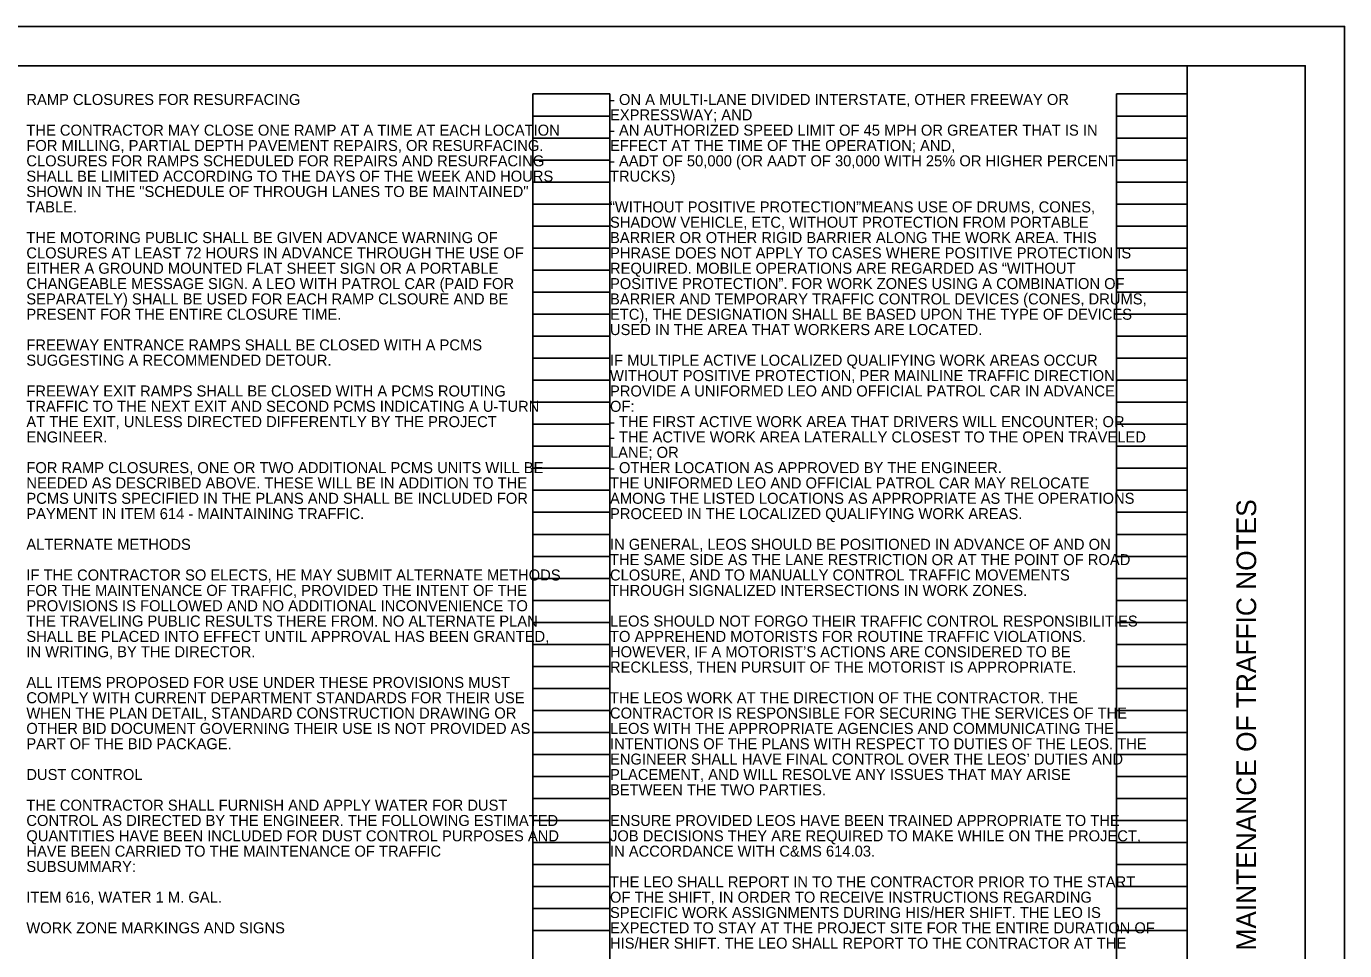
# Model space of a CAD drawing. Extents: x 0 to 34, y 0 to 22.
# Drawn here: x 17.24 to 34, y 10.25 to 22 of the extents above; entities that cross this region are included whole.
import ezdxf

# ---------------------------------------------------------------- set-up
doc = ezdxf.new("R2010")
doc.units = 0
for name, color, linetype in [('SH_Border', 7, 'Continuous'), ('SH_Cut_Line', 7, 'Continuous'), ('SH_Data', 7, 'Continuous'), ('SH_Text', 7, 'Continuous')]:
    doc.layers.add(name, color=color, linetype=linetype)

msp = doc.modelspace()

# ---------------------------------------------------------------- linework, layer by layer
at = {"layer": 'SH_Border'}
msp.add_line((32, 0.5), (32, 21.5), dxfattribs=at)
msp.add_lwpolyline([(1.5, 21.5), (33.5, 21.5), (33.5, 0.5), (1.5, 0.5)], close=True, dxfattribs=at)
at = {"layer": 'SH_Cut_Line'}
msp.add_lwpolyline([(0, 0), (34, 0), (34, 22), (0, 22)], close=True, dxfattribs=at)
at = {"layer": 'SH_Data'}
for p, q in [((23.68, 0.98), (23.68, 21.14)), ((23.68, 21.14), (24.66, 21.14)), ((24.66, 0.98), (24.66, 21.14)), ((31.1, 0.98), (31.1, 21.14)), ((31.1, 21.14), (32, 21.14)), ((32, 0.98), (32, 21.14)), ((23.68, 20.86), (24.66, 20.86)), ((31.1, 20.86), (32, 20.86)), ((23.68, 20.58), (24.66, 20.58)), ((31.1, 20.58), (32, 20.58)), ((23.68, 20.3), (24.66, 20.3)), ((31.1, 20.3), (32, 20.3)), ((23.68, 20.02), (24.66, 20.02)), ((31.1, 20.02), (32, 20.02)), ((23.68, 19.74), (24.66, 19.74)), ((31.1, 19.74), (32, 19.74)), ((23.68, 19.46), (24.66, 19.46)), ((31.1, 19.46), (32, 19.46)), ((23.68, 19.18), (24.66, 19.18)), ((31.1, 19.18), (32, 19.18)), ((23.68, 18.9), (24.66, 18.9)), ((31.1, 18.9), (32, 18.9)), ((23.68, 18.62), (24.66, 18.62)), ((31.1, 18.62), (32, 18.62)), ((23.68, 18.34), (24.66, 18.34)), ((31.1, 18.34), (32, 18.34)), ((23.68, 18.06), (24.66, 18.06)), ((31.1, 18.06), (32, 18.06)), ((23.68, 17.78), (24.66, 17.78)), ((31.1, 17.78), (32, 17.78)), ((23.68, 17.5), (24.66, 17.5)), ((31.1, 17.5), (32, 17.5)), ((23.68, 17.22), (24.66, 17.22)), ((31.1, 17.22), (32, 17.22)), ((23.68, 16.94), (24.66, 16.94)), ((31.1, 16.94), (32, 16.94)), ((23.68, 16.66), (24.66, 16.66)), ((31.1, 16.66), (32, 16.66)), ((23.68, 16.38), (24.66, 16.38)), ((31.1, 16.38), (32, 16.38)), ((23.68, 16.1), (24.66, 16.1)), ((31.1, 16.1), (32, 16.1)), ((23.68, 15.82), (24.66, 15.82)), ((31.1, 15.82), (32, 15.82)), ((23.68, 15.54), (24.66, 15.54)), ((31.1, 15.54), (32, 15.54)), ((23.68, 15.26), (24.66, 15.26)), ((31.1, 15.26), (32, 15.26)), ((23.68, 14.98), (24.66, 14.98)), ((31.1, 14.98), (32, 14.98)), ((23.68, 14.7), (24.66, 14.7)), ((31.1, 14.7), (32, 14.7)), ((23.68, 14.42), (24.66, 14.42)), ((31.1, 14.42), (32, 14.42)), ((23.68, 14.14), (24.66, 14.14)), ((31.1, 14.14), (32, 14.14)), ((23.68, 13.86), (24.66, 13.86)), ((31.1, 13.86), (32, 13.86)), ((23.68, 13.58), (24.66, 13.58)), ((31.1, 13.58), (32, 13.58)), ((23.68, 13.3), (24.66, 13.3)), ((31.1, 13.3), (32, 13.3)), ((23.68, 13.02), (24.66, 13.02)), ((31.1, 13.02), (32, 13.02)), ((23.68, 12.74), (24.66, 12.74)), ((31.1, 12.74), (32, 12.74)), ((23.68, 12.46), (24.66, 12.46)), ((31.1, 12.46), (32, 12.46)), ((23.68, 12.18), (24.66, 12.18)), ((31.1, 12.18), (32, 12.18)), ((23.68, 11.9), (24.66, 11.9)), ((31.1, 11.9), (32, 11.9)), ((23.68, 11.62), (24.66, 11.62)), ((31.1, 11.62), (32, 11.62)), ((23.68, 11.34), (24.66, 11.34)), ((31.1, 11.34), (32, 11.34)), ((23.68, 11.06), (24.66, 11.06)), ((31.1, 11.06), (32, 11.06)), ((23.68, 10.78), (24.66, 10.78)), ((31.1, 10.78), (32, 10.78)), ((23.68, 10.5), (24.66, 10.5)), ((31.1, 10.5), (32, 10.5))]:
    msp.add_line(p, q, dxfattribs=at)

# ---------------------------------------------------------------- texts
msp.add_text('MAINTENANCE OF TRAFFIC NOTES', height=0.25, rotation=90, dxfattribs=at).set_placement((32.875, 10.247))
at = {"layer": 'SH_Text'}
for s, p in [('RAMP CLOSURES FOR RESURFACING', (17.24, 21)), ('- ON A MULTI-LANE DIVIDED INTERSTATE, OTHER FREEWAY OR ', (24.66, 21)), ('EXPRESSWAY; AND ', (24.66, 20.805)), ('THE CONTRACTOR MAY CLOSE ONE RAMP AT A TIME AT EACH LOCATION ', (17.24, 20.61)), ('- AN AUTHORIZED SPEED LIMIT OF 45 MPH OR GREATER THAT IS IN ', (24.66, 20.61)), ('FOR MILLING, PARTIAL DEPTH PAVEMENT REPAIRS, OR RESURFACING. ', (17.24, 20.415)), ('EFFECT AT THE TIME OF THE OPERATION; AND, ', (24.66, 20.415)), ('CLOSURES FOR RAMPS SCHEDULED FOR REPAIRS AND RESURFACING ', (17.24, 20.22)), ('- AADT OF 50,000 (OR AADT OF 30,000 WITH 25% OR HIGHER PERCENT ', (24.66, 20.22)), ('SHALL BE LIMITED ACCORDING TO THE DAYS OF THE WEEK AND HOURS ', (17.24, 20.025)), ('TRUCKS) ', (24.66, 20.025)), ('SHOWN IN THE "SCHEDULE OF THROUGH LANES TO BE MAINTAINED" ', (17.24, 19.83)), ('TABLE.', (17.24, 19.634)), ('“WITHOUT POSITIVE PROTECTION”MEANS USE OF DRUMS, CONES, ', (24.66, 19.634)), ('SHADOW VEHICLE, ETC, WITHOUT PROTECTION FROM PORTABLE ', (24.66, 19.439)), ('THE MOTORING PUBLIC SHALL BE GIVEN ADVANCE WARNING OF ', (17.24, 19.244)), ('BARRIER OR OTHER RIGID BARRIER ALONG THE WORK AREA. THIS ', (24.66, 19.244)), ('CLOSURES AT LEAST 72 HOURS IN ADVANCE THROUGH THE USE OF ', (17.24, 19.049)), ('PHRASE DOES NOT APPLY TO CASES WHERE POSITIVE PROTECTION IS ', (24.66, 19.049)), ('EITHER A GROUND MOUNTED FLAT SHEET SIGN OR A PORTABLE ', (17.24, 18.854)), ('REQUIRED. MOBILE OPERATIONS ARE REGARDED AS “WITHOUT ', (24.66, 18.854)), ('CHANGEABLE MESSAGE SIGN. A LEO WITH PATROL CAR (PAID FOR ', (17.24, 18.659)), ('POSITIVE PROTECTION”. FOR WORK ZONES USING A COMBINATION OF ', (24.66, 18.659)), ('SEPARATELY) SHALL BE USED FOR EACH RAMP CLSOURE AND BE ', (17.24, 18.464)), ('BARRIER AND TEMPORARY TRAFFIC CONTROL DEVICES (CONES, DRUMS, ', (24.66, 18.464)), ('PRESENT FOR THE ENTIRE CLOSURE TIME.', (17.24, 18.269)), ('ETC), THE DESIGNATION SHALL BE BASED UPON THE TYPE OF DEVICES ', (24.66, 18.269)), ('USED IN THE AREA THAT WORKERS ARE LOCATED. ', (24.66, 18.074)), ('FREEWAY ENTRANCE RAMPS SHALL BE CLOSED WITH A PCMS ', (17.24, 17.879)), ('SUGGESTING A RECOMMENDED DETOUR.', (17.24, 17.684)), ('IF MULTIPLE ACTIVE LOCALIZED QUALIFYING WORK AREAS OCCUR ', (24.66, 17.684)), ('WITHOUT POSITIVE PROTECTION, PER MAINLINE TRAFFIC DIRECTION, ', (24.66, 17.489)), ('FREEWAY EXIT RAMPS SHALL BE CLOSED WITH A PCMS ROUTING ', (17.24, 17.293)), ('PROVIDE A UNIFORMED LEO AND OFFICIAL PATROL CAR IN ADVANCE ', (24.66, 17.293)), ('TRAFFIC TO THE NEXT EXIT AND SECOND PCMS INDICATING A U-TURN ', (17.24, 17.098)), ('OF:', (24.66, 17.098)), ('AT THE EXIT, UNLESS DIRECTED DIFFERENTLY BY THE PROJECT ', (17.24, 16.903)), ('- THE FIRST ACTIVE WORK AREA THAT DRIVERS WILL ENCOUNTER; OR ', (24.66, 16.903)), ('ENGINEER.', (17.24, 16.708)), ('- THE ACTIVE WORK AREA LATERALLY CLOSEST TO THE OPEN TRAVELED ', (24.66, 16.708)), ('LANE; OR ', (24.66, 16.513)), ('FOR RAMP CLOSURES, ONE OR TWO ADDITIONAL PCMS UNITS WILL BE ', (17.24, 16.318)), ('- OTHER LOCATION AS APPROVED BY THE ENGINEER. ', (24.66, 16.318)), ('NEEDED AS DESCRIBED ABOVE. THESE WILL BE IN ADDITION TO THE ', (17.24, 16.123)), ('THE UNIFORMED LEO AND OFFICIAL PATROL CAR MAY RELOCATE ', (24.66, 16.123)), ('PCMS UNITS SPECIFIED IN THE PLANS AND SHALL BE INCLUDED FOR ', (17.24, 15.928)), ('AMONG THE LISTED LOCATIONS AS APPROPRIATE AS THE OPERATIONS ', (24.66, 15.928)), ('PAYMENT IN ITEM 614 - MAINTAINING TRAFFIC.', (17.24, 15.733)), ('PROCEED IN THE LOCALIZED QUALIFYING WORK AREAS.', (24.66, 15.733)), ('ALTERNATE METHODS', (17.24, 15.343)), ('IN GENERAL, LEOS SHOULD BE POSITIONED IN ADVANCE OF AND ON ', (24.66, 15.343)), ('THE SAME SIDE AS THE LANE RESTRICTION OR AT THE POINT OF ROAD ', (24.66, 15.148)), ('IF THE CONTRACTOR SO ELECTS, HE MAY SUBMIT ALTERNATE METHODS ', (17.24, 14.953)), ('CLOSURE, AND TO MANUALLY CONTROL TRAFFIC MOVEMENTS ', (24.66, 14.953)), ('FOR THE MAINTENANCE OF TRAFFIC, PROVIDED THE INTENT OF THE ', (17.24, 14.757)), ('THROUGH SIGNALIZED INTERSECTIONS IN WORK ZONES. ', (24.66, 14.757)), ('PROVISIONS IS FOLLOWED AND NO ADDITIONAL INCONVENIENCE TO ', (17.24, 14.562)), ('THE TRAVELING PUBLIC RESULTS THERE FROM. NO ALTERNATE PLAN ', (17.24, 14.367)), ('LEOS SHOULD NOT FORGO THEIR TRAFFIC CONTROL RESPONSIBILITIES ', (24.66, 14.367)), ('SHALL BE PLACED INTO EFFECT UNTIL APPROVAL HAS BEEN GRANTED, ', (17.24, 14.172)), ('TO APPREHEND MOTORISTS FOR ROUTINE TRAFFIC VIOLATIONS. ', (24.66, 14.172)), ('IN WRITING, BY THE DIRECTOR.', (17.24, 13.977)), ('HOWEVER, IF A MOTORIST’S ACTIONS ARE CONSIDERED TO BE ', (24.66, 13.977)), ('RECKLESS, THEN PURSUIT OF THE MOTORIST IS APPROPRIATE. ', (24.66, 13.782)), ('ALL ITEMS PROPOSED FOR USE UNDER THESE PROVISIONS MUST ', (17.24, 13.587)), ('COMPLY WITH CURRENT DEPARTMENT STANDARDS FOR THEIR USE ', (17.24, 13.392)), ('THE LEOS WORK AT THE DIRECTION OF THE CONTRACTOR. THE ', (24.66, 13.392)), ('WHEN THE PLAN DETAIL, STANDARD CONSTRUCTION DRAWING OR ', (17.24, 13.197)), ('CONTRACTOR IS RESPONSIBLE FOR SECURING THE SERVICES OF THE ', (24.66, 13.197)), ('OTHER BID DOCUMENT GOVERNING THEIR USE IS NOT PROVIDED AS ', (17.24, 13.002)), ('LEOS WITH THE APPROPRIATE AGENCIES AND COMMUNICATING THE ', (24.66, 13.002)), ('PART OF THE BID PACKAGE.', (17.24, 12.807)), ('INTENTIONS OF THE PLANS WITH RESPECT TO DUTIES OF THE LEOS. THE ', (24.66, 12.807)), ('ENGINEER SHALL HAVE FINAL CONTROL OVER THE LEOS’ DUTIES AND ', (24.66, 12.612)), ('DUST CONTROL', (17.24, 12.416)), ('PLACEMENT, AND WILL RESOLVE ANY ISSUES THAT MAY ARISE ', (24.66, 12.416)), ('BETWEEN THE TWO PARTIES. ', (24.66, 12.221)), ('THE CONTRACTOR SHALL FURNISH AND APPLY WATER FOR DUST ', (17.24, 12.026)), ('CONTROL AS DIRECTED BY THE ENGINEER. THE FOLLOWING ESTIMATED ', (17.24, 11.831)), ('ENSURE PROVIDED LEOS HAVE BEEN TRAINED APPROPRIATE TO THE ', (24.66, 11.831)), ('QUANTITIES HAVE BEEN INCLUDED FOR DUST CONTROL PURPOSES AND ', (17.24, 11.636)), ('JOB DECISIONS THEY ARE REQUIRED TO MAKE WHILE ON THE PROJECT, ', (24.66, 11.636)), ('HAVE BEEN CARRIED TO THE MAINTENANCE OF TRAFFIC ', (17.24, 11.441)), ('IN ACCORDANCE WITH C&MS 614.03.', (24.66, 11.441)), ('SUBSUMMARY: ', (17.24, 11.246)), ('THE LEO SHALL REPORT IN TO THE CONTRACTOR PRIOR TO THE START ', (24.66, 11.051)), ('ITEM 616, WATER 1 M. GAL. ', (17.24, 10.856)), ('OF THE SHIFT, IN ORDER TO RECEIVE INSTRUCTIONS REGARDING ', (24.66, 10.856)), ('SPECIFIC WORK ASSIGNMENTS DURING HIS/HER SHIFT. THE LEO IS ', (24.66, 10.661)), ('WORK ZONE MARKINGS AND SIGNS', (17.24, 10.466)), ('EXPECTED TO STAY AT THE PROJECT SITE FOR THE ENTIRE DURATION OF ', (24.66, 10.466)), ('HIS/HER SHIFT. THE LEO SHALL REPORT TO THE CONTRACTOR AT THE ', (24.66, 10.271))]:
    msp.add_text(s, height=0.14, dxfattribs=at).set_placement(p)

doc.saveas('drawing.dxf')
